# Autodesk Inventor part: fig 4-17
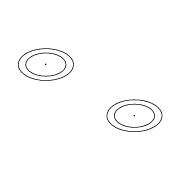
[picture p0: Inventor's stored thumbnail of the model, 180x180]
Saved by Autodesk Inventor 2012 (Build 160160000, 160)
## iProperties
Created: 2005-02
Part Number: fig 4-17
Document SubType Name: Modeling
Designer: CADCIM
Manufacturer: Standard
Standards Organization: Custom
Density: 1 g/cm^3
Material: Default
Author: CADCIM
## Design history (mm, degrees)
sketch "Sketch1"
  geometry: C1 r 7.935 at (-23.563, 7.599); C2 r 7.935 at (12.452, 7.599); C3 r 5.782 at (-23.563, 7.599); C4 r 5.782 at (12.452, 7.599)
  constraints: 4 centre point, 1 coincident, 1 equal radius, 1 other
